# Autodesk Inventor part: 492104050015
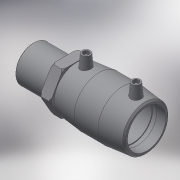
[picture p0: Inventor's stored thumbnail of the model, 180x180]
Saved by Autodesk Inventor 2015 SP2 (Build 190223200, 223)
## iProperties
Created: 2017-06
Part Number: 492104050015
Material: Generic
Description: PLASSON Male Transition Coupler 50 x 1.1/2"
Document SubType Name: Modeling
Designer: KIM
Mass: 214.805 g
Surface Area: 550.599 cm^2
Volume: 214.805 cm^3
Density: 1 g/cm^3
Appearance: Default
Author: KIM
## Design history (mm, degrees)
derived "492104.ipt"
feature "Solid1::492104.ipt"
tag "TaggingFeature1"
body "Solid1"
other parameters: "d0" = 101, "d2" = 67, "d3" = 49, "d4" = 33.66667, "d5" = 60.3, "d6" = 47.5, "d8" = 168 deg, "d10" = 19.6, "d11" = 6.53333, "d29" = 51, "d30" = 14, "d31" = 35.35, "d34" = 5 deg, "d41" = 4, "d42" = 14, "d43" = 0, "d48" = 3, "d49" = 0, "d57" = 38, "d58" = 47.803, "d59" = 38.2424, "d60" = 32.4, "d61" = 67, "d62" = 0.95606, "d65" = 2.01, "d70" = 0.1, "d71" = 36, "d72" = 9, "d73" = 19.6, "d75" = 0, "L_" = 137, "L_1" = 49, "D_1" = 67, "A_" = 51, "d_2" = 12, "L_2" = 36, "D_" = 38, "R_" = 47.803
